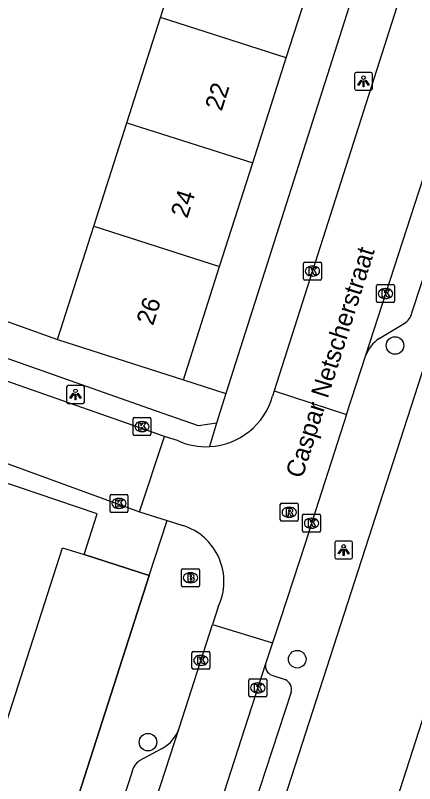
# Model space of a CAD drawing. Extents: x 162812 to 163818, y 381639 to 382470.
# Drawn here: x 163218.85 to 163241.12, y 382068.45 to 382111.27 of the extents above; entities that cross this region are included whole.
import ezdxf

# ---------------------------------------------------------------- set-up
doc = ezdxf.new("R2010")
doc.units = 0
for name, color, linetype in [('IMGEO_Boom', 7, 'Continuous'), ('IMGEO_Brandkraan', 7, 'Continuous'), ('IMGEO_Groenvoorziening', 7, 'Continuous'), ('IMGEO_Hek', 7, 'Continuous'), ('IMGEO_Kolk', 7, 'Continuous'), ('IMGEO_Lichtpunt', 7, 'Continuous'), ('IMGEO_Muur', 7, 'Continuous'), ('IMGEO_Openbare_ruimte_label', 7, 'Continuous'), ('IMGEO_Pand', 7, 'Continuous'), ('IMGEO_Pand_nummerreeks', 7, 'Continuous'), ('IMGEO_Rijbaan_lokaal_open', 7, 'Continuous'), ('IMGEO_Rioolput', 7, 'Continuous'), ('IMGEO_Voetpad_open', 7, 'Continuous')]:
    doc.layers.add(name, color=color, linetype=linetype)

msp = doc.modelspace()

# ---------------------------------------------------------------- linework, layer by layer
at = {"layer": 'IMGEO_Boom'}
for centre in [(163240.025, 382092.871), (163234.572, 382075.38), (163226.251, 382070.757)]:
    msp.add_circle(centre, 0.489, dxfattribs=at)
at = {"layer": 'IMGEO_Brandkraan'}
for p, q in [((163228.12, 382079.496), (163228.12, 382080.348)), ((163228.195, 382080.422), (163229.047, 382080.422)), ((163228.608, 382080.202), (163228.633, 382080.202)), ((163229.121, 382080.348), (163229.121, 382079.496)), ((163229.047, 382079.422), (163228.195, 382079.422)), ((163228.631, 382079.642), (163228.606, 382079.642))]:
    msp.add_line(p, q, dxfattribs=at)
for points in [[(163228.12, 382079.496), (163228.12, 382080.348)], [(163228.195, 382080.422), (163229.047, 382080.422)], [(163229.121, 382080.348), (163229.121, 382079.496)], [(163228.468, 382080.122), (163228.468, 382079.722), (163228.681, 382079.722)], [(163228.699, 382080.122), (163228.468, 382080.122)], [(163228.647, 382080.041), (163228.593, 382080.041), (163228.593, 382079.965)], [(163228.593, 382079.965), (163228.646, 382079.965)], [(163228.655, 382079.889), (163228.593, 382079.889), (163228.593, 382079.808)], [(163228.593, 382079.808), (163228.655, 382079.808)], [(163229.047, 382079.422), (163228.195, 382079.422)]]:
    msp.add_lwpolyline(points, dxfattribs=at)
for centre, radius, start, end in [((163228.197, 382080.346), 0.0765, 91.552, 178.448), ((163228.197, 382080.346), 0.0765, 91.552, 178.448), ((163229.045, 382080.346), 0.0765, 1.552, 88.448), ((163229.045, 382080.346), 0.0765, 1.552, 88.448), ((163228.648, 382080.003), 0.0379, 267.8285, 90.9355), ((163228.656, 382079.848), 0.0404, 269.8759, 90.5077), ((163228.687, 382079.973), 0.251, 268.6676, 293.5347), ((163228.703, 382079.977), 0.145, 59.4692, 91.5367), ((163228.728, 382080.024), 0.0922, 285.5137, 58.1501), ((163228.733, 382079.832), 0.105, 301.3115, 78.989), ((163228.197, 382079.498), 0.0765, 181.552, 268.448), ((163228.197, 382079.498), 0.0765, 181.552, 268.448), ((163229.045, 382079.498), 0.0765, 271.552, 358.448), ((163229.045, 382079.498), 0.0765, 271.552, 358.448)]:
    msp.add_arc(centre, radius, start, end, dxfattribs=at)
for centre, major_axis, ratio, start_param, end_param in [((163228.607, 382079.922), (-0.387, 0.002), 0.722429, 4.712389, 7.853982), ((163228.632, 382079.922), (-0.39, 0.002), 0.717154, 1.570796, 4.712389)]:
    msp.add_ellipse(centre, major_axis=major_axis, ratio=ratio, start_param=start_param, end_param=end_param, dxfattribs=at)
at = {"layer": 'IMGEO_Groenvoorziening'}
for points in [[(163208.13, 382097.894), (163221.207, 382093.209)], [(163228.224, 382090.964), (163230.592, 382090.193)]]:
    msp.add_lwpolyline(points, dxfattribs=at)
at = {"layer": 'IMGEO_Hek'}
msp.add_lwpolyline([(163208.13, 382097.894), (163221.207, 382093.209)], dxfattribs=at)
at = {"layer": 'IMGEO_Kolk'}
for p, q in [((163234.919, 382096.592), (163234.919, 382097.444)), ((163234.994, 382097.518), (163235.846, 382097.518)), ((163235.407, 382097.298), (163235.432, 382097.298)), ((163235.92, 382097.444), (163235.92, 382096.592)), ((163235.846, 382096.518), (163234.994, 382096.518)), ((163235.43, 382096.738), (163235.405, 382096.738)), ((163238.994, 382095.338), (163238.994, 382096.19)), ((163239.069, 382096.264), (163239.921, 382096.264)), ((163239.482, 382096.044), (163239.507, 382096.044)), ((163239.995, 382096.19), (163239.995, 382095.338)), ((163239.921, 382095.264), (163239.069, 382095.264)), ((163239.505, 382095.484), (163239.48, 382095.484)), ((163225.416, 382087.925), (163225.416, 382088.777)), ((163225.491, 382088.851), (163226.343, 382088.851)), ((163226.417, 382088.777), (163226.417, 382087.925)), ((163225.904, 382088.631), (163225.929, 382088.631)), ((163225.927, 382088.071), (163225.902, 382088.071)), ((163226.343, 382087.851), (163225.491, 382087.851)), ((163224.133, 382083.64), (163224.133, 382084.492)), ((163224.208, 382084.566), (163225.06, 382084.566)), ((163225.134, 382084.492), (163225.134, 382083.64)), ((163224.621, 382084.346), (163224.646, 382084.346)), ((163224.644, 382083.786), (163224.619, 382083.786)), ((163225.06, 382083.566), (163224.208, 382083.566)), ((163234.87, 382082.538), (163234.87, 382083.39)), ((163234.945, 382083.464), (163235.797, 382083.464)), ((163235.358, 382083.244), (163235.383, 382083.244)), ((163235.871, 382083.39), (163235.871, 382082.538)), ((163235.797, 382082.464), (163234.945, 382082.464)), ((163235.381, 382082.684), (163235.356, 382082.684)), ((163228.702, 382074.892), (163228.702, 382075.744)), ((163228.777, 382075.818), (163229.629, 382075.818)), ((163229.19, 382075.598), (163229.215, 382075.598)), ((163229.703, 382075.744), (163229.703, 382074.892)), ((163229.213, 382075.038), (163229.188, 382075.038)), ((163229.629, 382074.818), (163228.777, 382074.818)), ((163231.875, 382073.359), (163231.875, 382074.211)), ((163231.95, 382074.285), (163232.802, 382074.285)), ((163232.876, 382074.211), (163232.876, 382073.359)), ((163232.363, 382074.065), (163232.388, 382074.065)), ((163232.386, 382073.505), (163232.361, 382073.505)), ((163232.802, 382073.285), (163231.95, 382073.285))]:
    msp.add_line(p, q, dxfattribs=at)
for points in [[(163234.919, 382096.592), (163234.919, 382097.444)], [(163234.994, 382097.518), (163235.846, 382097.518)], [(163235.92, 382097.444), (163235.92, 382096.592)], [(163235.24, 382097.218), (163235.363, 382097.218), (163235.363, 382097.067), (163235.493, 382097.218), (163235.657, 382097.218), (163235.511, 382097.067), (163235.664, 382096.818), (163235.512, 382096.818), (163235.427, 382096.982), (163235.363, 382096.915), (163235.363, 382096.818), (163235.24, 382096.818), (163235.24, 382097.218)], [(163235.846, 382096.518), (163234.994, 382096.518)], [(163238.994, 382095.338), (163238.994, 382096.19)], [(163239.069, 382096.264), (163239.921, 382096.264)], [(163239.995, 382096.19), (163239.995, 382095.338)], [(163239.315, 382095.964), (163239.438, 382095.964), (163239.438, 382095.813), (163239.568, 382095.964), (163239.732, 382095.964), (163239.586, 382095.813), (163239.739, 382095.564), (163239.587, 382095.564), (163239.502, 382095.728), (163239.438, 382095.661), (163239.438, 382095.564), (163239.315, 382095.564), (163239.315, 382095.964)], [(163239.921, 382095.264), (163239.069, 382095.264)], [(163225.416, 382087.925), (163225.416, 382088.777)], [(163225.491, 382088.851), (163226.343, 382088.851)], [(163226.417, 382088.777), (163226.417, 382087.925)], [(163225.737, 382088.551), (163225.86, 382088.551), (163225.86, 382088.4), (163225.99, 382088.551), (163226.154, 382088.551), (163226.008, 382088.4), (163226.161, 382088.151), (163226.009, 382088.151), (163225.924, 382088.315), (163225.86, 382088.248), (163225.86, 382088.151), (163225.737, 382088.151), (163225.737, 382088.551)], [(163226.343, 382087.851), (163225.491, 382087.851)], [(163224.133, 382083.64), (163224.133, 382084.492)], [(163224.208, 382084.566), (163225.06, 382084.566)], [(163225.134, 382084.492), (163225.134, 382083.64)], [(163224.454, 382084.266), (163224.577, 382084.266), (163224.577, 382084.115), (163224.707, 382084.266), (163224.871, 382084.266), (163224.725, 382084.115), (163224.878, 382083.866), (163224.726, 382083.866), (163224.641, 382084.03), (163224.577, 382083.963), (163224.577, 382083.866), (163224.454, 382083.866), (163224.454, 382084.266)], [(163225.06, 382083.566), (163224.208, 382083.566)], [(163234.87, 382082.538), (163234.87, 382083.39)], [(163234.945, 382083.464), (163235.797, 382083.464)], [(163235.191, 382083.164), (163235.314, 382083.164), (163235.314, 382083.013), (163235.444, 382083.164), (163235.608, 382083.164), (163235.462, 382083.013), (163235.615, 382082.764), (163235.463, 382082.764), (163235.378, 382082.928), (163235.314, 382082.861), (163235.314, 382082.764), (163235.191, 382082.764), (163235.191, 382083.164)], [(163235.871, 382083.39), (163235.871, 382082.538)], [(163235.797, 382082.464), (163234.945, 382082.464)], [(163228.702, 382074.892), (163228.702, 382075.744)], [(163228.777, 382075.818), (163229.629, 382075.818)], [(163229.023, 382075.518), (163229.146, 382075.518), (163229.146, 382075.367), (163229.276, 382075.518), (163229.44, 382075.518), (163229.294, 382075.367), (163229.447, 382075.118), (163229.295, 382075.118), (163229.21, 382075.282), (163229.146, 382075.215), (163229.146, 382075.118), (163229.023, 382075.118), (163229.023, 382075.518)], [(163229.703, 382075.744), (163229.703, 382074.892)], [(163229.629, 382074.818), (163228.777, 382074.818)], [(163231.875, 382073.359), (163231.875, 382074.211)], [(163231.95, 382074.285), (163232.802, 382074.285)], [(163232.876, 382074.211), (163232.876, 382073.359)], [(163232.196, 382073.985), (163232.319, 382073.985), (163232.319, 382073.834), (163232.449, 382073.985), (163232.613, 382073.985), (163232.467, 382073.834), (163232.62, 382073.585), (163232.468, 382073.585), (163232.383, 382073.749), (163232.319, 382073.682), (163232.319, 382073.585), (163232.196, 382073.585), (163232.196, 382073.985)], [(163232.802, 382073.285), (163231.95, 382073.285)]]:
    msp.add_lwpolyline(points, dxfattribs=at)
for centre, start, end in [((163234.996, 382097.442), 91.552, 178.448), ((163234.996, 382097.442), 91.552, 178.448), ((163235.844, 382097.442), 1.552, 88.448), ((163235.844, 382097.442), 1.552, 88.448), ((163234.996, 382096.594), 181.552, 268.448), ((163234.996, 382096.594), 181.552, 268.448), ((163235.844, 382096.594), 271.552, 358.448), ((163235.844, 382096.594), 271.552, 358.448), ((163239.071, 382096.188), 91.552, 178.448), ((163239.071, 382096.188), 91.552, 178.448), ((163239.919, 382096.188), 1.552, 88.448), ((163239.919, 382096.188), 1.552, 88.448), ((163239.071, 382095.34), 181.552, 268.448), ((163239.071, 382095.34), 181.552, 268.448), ((163239.919, 382095.34), 271.552, 358.448), ((163239.919, 382095.34), 271.552, 358.448), ((163225.493, 382088.775), 91.552, 178.448), ((163225.493, 382088.775), 91.552, 178.448), ((163226.341, 382088.775), 1.552, 88.448), ((163226.341, 382088.775), 1.552, 88.448), ((163225.493, 382087.927), 181.552, 268.448), ((163225.493, 382087.927), 181.552, 268.448), ((163226.341, 382087.927), 271.552, 358.448), ((163226.341, 382087.927), 271.552, 358.448), ((163224.21, 382084.49), 91.552, 178.448), ((163224.21, 382084.49), 91.552, 178.448), ((163225.058, 382084.49), 1.552, 88.448), ((163225.058, 382084.49), 1.552, 88.448), ((163224.21, 382083.642), 181.552, 268.448), ((163224.21, 382083.642), 181.552, 268.448), ((163225.058, 382083.642), 271.552, 358.448), ((163225.058, 382083.642), 271.552, 358.448), ((163234.947, 382083.388), 91.552, 178.448), ((163234.947, 382083.388), 91.552, 178.448), ((163235.795, 382083.388), 1.552, 88.448), ((163235.795, 382083.388), 1.552, 88.448), ((163234.947, 382082.54), 181.552, 268.448), ((163234.947, 382082.54), 181.552, 268.448), ((163235.795, 382082.54), 271.552, 358.448), ((163235.795, 382082.54), 271.552, 358.448), ((163228.779, 382075.742), 91.552, 178.448), ((163228.779, 382075.742), 91.552, 178.448), ((163229.627, 382075.742), 1.552, 88.448), ((163229.627, 382075.742), 1.552, 88.448), ((163228.779, 382074.894), 181.552, 268.448), ((163228.779, 382074.894), 181.552, 268.448), ((163229.627, 382074.894), 271.552, 358.448), ((163229.627, 382074.894), 271.552, 358.448), ((163231.952, 382074.209), 91.552, 178.448), ((163231.952, 382074.209), 91.552, 178.448), ((163232.8, 382074.209), 1.552, 88.448), ((163232.8, 382074.209), 1.552, 88.448), ((163231.952, 382073.361), 181.552, 268.448), ((163231.952, 382073.361), 181.552, 268.448), ((163232.8, 382073.361), 271.552, 358.448), ((163232.8, 382073.361), 271.552, 358.448)]:
    msp.add_arc(centre, 0.0765, start, end, dxfattribs=at)
for centre, major_axis, ratio, start_param, end_param in [((163235.406, 382097.018), (-0.387, 0.002), 0.722429, 4.712389, 7.853982), ((163235.431, 382097.018), (-0.39, 0.002), 0.717154, 1.570796, 4.712389), ((163239.481, 382095.764), (-0.387, 0.002), 0.722429, 4.712389, 7.853982), ((163239.506, 382095.764), (-0.39, 0.002), 0.717154, 1.570796, 4.712389), ((163225.903, 382088.351), (-0.387, 0.002), 0.722429, 4.712389, 7.853982), ((163225.928, 382088.351), (-0.39, 0.002), 0.717154, 1.570796, 4.712389), ((163224.62, 382084.066), (-0.387, 0.002), 0.722429, 4.712389, 7.853982), ((163224.645, 382084.066), (-0.39, 0.002), 0.717154, 1.570796, 4.712389), ((163235.357, 382082.964), (-0.387, 0.002), 0.722429, 4.712389, 7.853982), ((163235.382, 382082.964), (-0.39, 0.002), 0.717154, 1.570796, 4.712389), ((163229.189, 382075.318), (-0.387, 0.002), 0.722429, 4.712389, 7.853982), ((163229.214, 382075.318), (-0.39, 0.002), 0.717154, 1.570796, 4.712389), ((163232.362, 382073.785), (-0.387, 0.002), 0.722429, 4.712389, 7.853982), ((163232.387, 382073.785), (-0.39, 0.002), 0.717154, 1.570796, 4.712389)]:
    msp.add_ellipse(centre, major_axis=major_axis, ratio=ratio, start_param=start_param, end_param=end_param, dxfattribs=at)
at = {"layer": 'IMGEO_Lichtpunt'}
for p, q in [((163237.768, 382107.999), (163237.768, 382107.192)), ((163237.768, 382107.999), (163237.768, 382107.192)), ((163238.67, 382108.094), (163237.862, 382108.094)), ((163238.67, 382108.094), (163237.862, 382108.094)), ((163238.764, 382107.192), (163238.764, 382107.999)), ((163238.764, 382107.192), (163238.764, 382107.999)), ((163237.862, 382107.098), (163238.67, 382107.098)), ((163237.862, 382107.098), (163238.67, 382107.098)), ((163221.712, 382090.543), (163221.712, 382089.736)), ((163221.712, 382090.543), (163221.712, 382089.736)), ((163222.614, 382090.638), (163221.806, 382090.638)), ((163222.614, 382090.638), (163221.806, 382090.638)), ((163222.708, 382089.736), (163222.708, 382090.543)), ((163222.708, 382089.736), (163222.708, 382090.543)), ((163221.806, 382089.642), (163222.614, 382089.642)), ((163221.806, 382089.642), (163222.614, 382089.642)), ((163236.666, 382081.873), (163236.666, 382081.066)), ((163236.666, 382081.873), (163236.666, 382081.066)), ((163237.568, 382081.968), (163236.76, 382081.968)), ((163237.568, 382081.968), (163236.76, 382081.968)), ((163237.662, 382081.066), (163237.662, 382081.873)), ((163237.662, 382081.066), (163237.662, 382081.873)), ((163236.76, 382080.972), (163237.568, 382080.972)), ((163236.76, 382080.972), (163237.568, 382080.972))]:
    msp.add_line(p, q, dxfattribs=at)
for points in [[(163238.142, 382107.663), (163238.181, 382107.635), (163237.993, 382107.373), (163237.955, 382107.4), (163238.142, 382107.663)], [(163238.244, 382107.615), (163238.291, 382107.615), (163238.291, 382107.293), (163238.244, 382107.293), (163238.244, 382107.615)], [(163238.354, 382107.635), (163238.392, 382107.662), (163238.579, 382107.4), (163238.54, 382107.372), (163238.354, 382107.635)], [(163222.086, 382090.207), (163222.125, 382090.179), (163221.937, 382089.917), (163221.899, 382089.944), (163222.086, 382090.207)], [(163222.188, 382090.159), (163222.235, 382090.159), (163222.235, 382089.837), (163222.188, 382089.837), (163222.188, 382090.159)], [(163222.298, 382090.179), (163222.336, 382090.206), (163222.523, 382089.944), (163222.484, 382089.916), (163222.298, 382090.179)], [(163237.04, 382081.537), (163237.079, 382081.509), (163236.891, 382081.247), (163236.853, 382081.274), (163237.04, 382081.537)], [(163237.142, 382081.489), (163237.189, 382081.489), (163237.189, 382081.167), (163237.142, 382081.167), (163237.142, 382081.489)], [(163237.252, 382081.509), (163237.29, 382081.536), (163237.477, 382081.274), (163237.438, 382081.246), (163237.252, 382081.509)]]:
    msp.add_lwpolyline(points, dxfattribs=at)
for centre in [(163238.267, 382107.797), (163222.211, 382090.341), (163237.165, 382081.671)]:
    msp.add_circle(centre, 0.0994, dxfattribs=at)
for centre, start, end in [((163237.862, 382107.999), 90, 180), ((163237.862, 382107.999), 90, 180), ((163238.67, 382107.999), 0, 90), ((163238.67, 382107.999), 0, 90), ((163237.862, 382107.192), 180, 270), ((163237.862, 382107.192), 180, 270), ((163238.67, 382107.192), 270, 0), ((163238.67, 382107.192), 270, 360), ((163221.806, 382090.543), 90, 180), ((163221.806, 382090.543), 90, 180), ((163222.614, 382090.543), 0, 90), ((163222.614, 382090.543), 0, 90), ((163221.806, 382089.736), 180, 270), ((163221.806, 382089.736), 180, 270), ((163222.614, 382089.736), 270, 0), ((163222.614, 382089.736), 270, 360), ((163236.76, 382081.873), 90, 180), ((163236.76, 382081.873), 90, 180), ((163237.568, 382081.873), 0, 90), ((163237.568, 382081.873), 0, 90), ((163236.76, 382081.066), 180, 270), ((163236.76, 382081.066), 180, 270), ((163237.568, 382081.066), 270, 0), ((163237.568, 382081.066), 270, 360)]:
    msp.add_arc(centre, 0.0946, start, end, dxfattribs=at)
at = {"layer": 'IMGEO_Muur'}
for points in [[(163222.696, 382081.21), (163226.318, 382080.043)], [(163226.318, 382080.043), (163212.368, 382036.722)]]:
    msp.add_lwpolyline(points, dxfattribs=at)
at = {"layer": 'IMGEO_Pand'}
for points in [[(163226.946, 382111.148), (163228.846, 382117.084)], [(163233.963, 382108.904), (163235.862, 382114.84)], [(163225.071, 382105.29), (163226.946, 382111.148)], [(163233.963, 382108.904), (163226.946, 382111.148)], [(163232.089, 382103.046), (163233.963, 382108.904)], [(163223.223, 382099.513), (163225.071, 382105.29)], [(163225.071, 382105.29), (163232.089, 382103.046)], [(163230.241, 382097.269), (163232.089, 382103.046)], [(163221.207, 382093.209), (163223.223, 382099.513)], [(163223.223, 382099.513), (163230.241, 382097.269)], [(163228.224, 382090.964), (163230.241, 382097.269)], [(163221.207, 382093.209), (163228.224, 382090.964)], [(163222.696, 382081.21), (163223.425, 382083.487), (163216.698, 382085.758)], [(163208.165, 382035.907), (163209.039, 382038.621), (163207.78, 382039.026), (163221.488, 382081.598), (163222.696, 382081.21)], [(163239.976, 382067.082), (163241.867, 382072.971)]]:
    msp.add_lwpolyline(points, dxfattribs=at)
at = {"layer": 'IMGEO_Rijbaan_lokaal_open'}
for points in [[(163241.269, 382115.279), (163241.135, 382114.908), (163233.288, 382090.334)], [(163238.39, 382092.328), (163245.241, 382113.426)], [(163227.165, 382087.79), (163174.984, 382106.106)], [(163174.269, 382101.829), (163214.509, 382087.698), (163225.781, 382083.598)], [(163237.319, 382089.03), (163238.39, 382092.328)], [(163233.288, 382090.334), (163233.194, 382090.04)], [(163233.288, 382090.334), (163237.319, 382089.03)], [(163237.319, 382089.03), (163236.982, 382087.992), (163235.59, 382083.659), (163235.028, 382081.889), (163233.619, 382077.585), (163233.191, 382076.29)], [(163225.781, 382083.598), (163227.165, 382087.79)], [(163227.944, 382087.547), (163227.165, 382087.79)], [(163225.781, 382083.598), (163227.323, 382083.11)], [(163227.323, 382083.11), (163228.194, 382082.834)], [(163230.166, 382078.298), (163229.848, 382077.312)], [(163227.986, 382071.536), (163229.848, 382077.312)], [(163229.848, 382077.312), (163233.191, 382076.29)], [(163233.191, 382076.29), (163232.808, 382075.129)], [(163232.808, 382075.129), (163219.286, 382033.294)], [(163215.005, 382031.688), (163227.986, 382071.536)]]:
    msp.add_lwpolyline(points, dxfattribs=at)
for centre, radius, start, end in [((163229.482, 382091.085), 3.856, 273.0802, 344.2793), ((163229.48, 382091.088), 3.86, 246.5533, 273.1087), ((163227.215, 382079.712), 3.272, 334.4019, 72.5916)]:
    msp.add_arc(centre, radius, start, end, dxfattribs=at)
at = {"layer": 'IMGEO_Rioolput'}
for p, q in [((163233.702, 382084.077), (163234.554, 382084.077)), ((163233.627, 382083.151), (163233.627, 382084.003)), ((163234.115, 382083.857), (163234.14, 382083.857)), ((163234.628, 382084.003), (163234.628, 382083.151)), ((163234.138, 382083.297), (163234.113, 382083.297)), ((163234.554, 382083.077), (163233.702, 382083.077))]:
    msp.add_line(p, q, dxfattribs=at)
for points in [[(163233.702, 382084.077), (163234.554, 382084.077)], [(163233.627, 382083.151), (163233.627, 382084.003)], [(163234.216, 382083.775), (163233.964, 382083.777), (163233.964, 382083.377)], [(163234.142, 382083.696), (163234.088, 382083.696), (163234.088, 382083.615)], [(163234.088, 382083.615), (163234.14, 382083.615)], [(163234.628, 382084.003), (163234.628, 382083.151)], [(163233.964, 382083.377), (163234.088, 382083.377), (163234.088, 382083.539), (163234.099, 382083.539)], [(163234.146, 382083.51), (163234.217, 382083.377), (163234.357, 382083.377), (163234.292, 382083.503)], [(163234.554, 382083.077), (163233.702, 382083.077)]]:
    msp.add_lwpolyline(points, dxfattribs=at)
for centre, radius, start, end in [((163233.704, 382084.001), 0.0765, 91.552, 178.448), ((163233.704, 382084.001), 0.0765, 91.552, 178.448), ((163234.552, 382084.001), 0.0765, 1.552, 88.448), ((163234.552, 382084.001), 0.0765, 1.552, 88.448), ((163234.124, 382083.804), 0.19, 274.7715, 282.9687), ((163234.148, 382083.6), 0.0964, 77.0061, 93.1865), ((163234.162, 382083.657), 0.0378, 276.6634, 79.6772), ((163234.215, 382083.665), 0.109, 350.3612, 89.416), ((163234.213, 382083.665), 0.112, 277.5842, 350.9817), ((163233.704, 382083.153), 0.0765, 181.552, 268.448), ((163233.704, 382083.153), 0.0765, 181.552, 268.448), ((163234.098, 382083.486), 0.0533, 26.0293, 88.6989), ((163234.197, 382083.45), 0.108, 29.5134, 73.7905), ((163234.552, 382083.153), 0.0765, 271.552, 358.448), ((163234.552, 382083.153), 0.0765, 271.552, 358.448)]:
    msp.add_arc(centre, radius, start, end, dxfattribs=at)
for centre, major_axis, ratio, start_param, end_param in [((163234.114, 382083.577), (-0.387, 0.002), 0.722429, 4.712389, 7.853982), ((163234.139, 382083.577), (-0.39, 0.002), 0.717154, 1.570796, 4.712389)]:
    msp.add_ellipse(centre, major_axis=major_axis, ratio=ratio, start_param=start_param, end_param=end_param, dxfattribs=at)
at = {"layer": 'IMGEO_Voetpad_open'}
for points in [[(163243.91, 382132.016), (163230.592, 382090.193)], [(163247.759, 382110.658), (163228.176, 382050.033), (163230.013, 382049.41), (163229.849, 382048.901)], [(163240.968, 382094.694), (163243.666, 382102.869)], [(163230.068, 382088.548), (163229.068, 382088.4), (163226.305, 382089.363), (163203.8, 382097.286)], [(163239.137, 382093.254), (163240.537, 382094.092)], [(163230.592, 382090.193), (163230.068, 382088.548)], [(163230.068, 382088.548), (163229.689, 382087.234)], [(163226.318, 382080.043), (163227.323, 382083.11)], [(163226.318, 382080.043), (163222.696, 382081.21)], [(163212.368, 382036.722), (163226.318, 382080.043)], [(163233.154, 382074.493), (163233.894, 382074.245)], [(163234.237, 382073.537), (163231.4, 382064.93)], [(163227.045, 382070.412), (163225.757, 382069.71)], [(163225.353, 382069.07), (163221.392, 382056.88)]]:
    msp.add_lwpolyline(points, dxfattribs=at)
for centre, radius, start, end in [((163240.074, 382094.879), 0.913, 300.4813, 348.3174), ((163240.365, 382091.499), 2.142, 124.9836, 157.2304), ((163233.368, 382075.021), 0.57, 169.1053, 247.9893), ((163233.642, 382073.686), 0.614, 345.9757, 65.7213), ((163226.1, 382072.159), 1.986, 298.4065, 341.7221), ((163226.31, 382068.913), 0.97, 124.7787, 170.697)]:
    msp.add_arc(centre, radius, start, end, dxfattribs=at)

# ---------------------------------------------------------------- texts
at = {"layer": 'IMGEO_Openbare_ruimte_label'}
msp.add_text('Caspar Netscherstraat', height=1, rotation=72.3623, dxfattribs=at).set_placement((163234.85, 382085.414))
at = {"layer": 'IMGEO_Pand_nummerreeks'}
for s, p in [('22', (163230.354, 382105.894)), ('24', (163228.442, 382099.917)), ('26', (163226.529, 382093.936))]:
    msp.add_text(s, height=1, rotation=72.26, dxfattribs=at).set_placement(p)

doc.saveas('drawing.dxf')
